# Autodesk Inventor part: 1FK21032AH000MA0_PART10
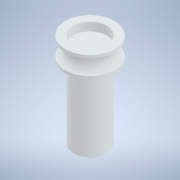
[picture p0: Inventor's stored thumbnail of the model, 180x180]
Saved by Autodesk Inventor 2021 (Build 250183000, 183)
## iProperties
Created: 2025-04
Part Number: 1FK21032AH000MA0_PART10
Material: Generic
Catalog Web Link: www.3dfindit.com
Description: -Servo synchronous motor
Document SubType Name: Modeling
Designer: psAdmin
Mass: 6.43867 g
Surface Area: 29.6592 cm^2
Volume: 6.43867 cm^3
Density: 1 g/cm^3
Appearance: PSOLRGB-212-217-219
Category: PARTsolutions
Title: 1FK21032AH000MA0_PART10
Author: Cadenas PARTsolutions
Comments: Servo synchronous motor
Sending System: PARTsolutions
Preprocessor: ST-DEVELOPER v19.3
PSOL_IDENT_0: {$CADENAS_DATA/23d-libs/siemens_ag/_cat_/45/10/1fk21032ah000ma0.prj},216 {VTYP=3D},{NB=1FK21032AH000
PSOL_IDENT_1: MA0_PART10},{LINA=1FK21032AH000MA0_PART10},{NN=1FK21032AH000MA0_PART10},{NOPRJ=TRUE},{DATE=19.08.202
PSOL_IDENT_2: 5 14:00:35},{GEOMDATE=30.07.2025 02:02:03},{VERSION=},{LINEID=10},{WBVAR=},{WBNUMERIC=}  {NB=1FK2103
PSOL_IDENT_3: 2AH000MA0_PART10},{LINA=1FK21032AH000MA0_PART10},{KT=DUMMY},{PREVIEW=../../../_pool_/14/8e/p_d211_xx
PSOL_IDENT_4: _00426j.png},{DESCSHORT=SIMOTICS S-1FK2 HD, SINAMICS S210 3AC 400V-480V, 0.59 Nm, 4500 rpm},{DESCLON
PSOL_IDENT_5: G=SIMOTICS S-1FK2 HD servo motor M0=0.64 Nm; PN = 0.28 kW at nN=4500 rpm (380-480 V); PN = 0.167 kW
PSOL_IDENT_6: at nN=2500 rpm (200-240 V); degree of protection IP64; cylindrical shaft D14 x 30 mm; absolute encod
PSOL_IDENT_7: er 22-bit + 12-bit multiturn (encoder AM22DQC); with OCC interface; plug size M17, rotatable; SIMOTI
PSOL_IDENT_8: CS S-1FK2 servomotorfor a wide range of uses in industrial environments. SIMOTICS S‑1FK2 servomotors
PSOL_IDENT_9: are compact synchronous motors with a high dynamic performance that set themselves apart as a resul
PSOL_IDENT_10: t of their high power density, degree of protection and overload capability. The motors are availabl
PSOL_IDENT_11: e in two variants: as High Dynamic variant (highest dynamic performance as a result of the low intri
PSOL_IDENT_12: nsic moment of inertia for applications demanding a high dynamic performance with low moved masses)
PSOL_IDENT_13: - and as Compact variant (precise and stable closed-loop control for medium up to large moved masses
PSOL_IDENT_14: as a result of a medium intrinsic moment of inertia). SIMOTICSS‑1FK2 servomotors fully exploit thei
PSOL_IDENT_15: r strengths in a system with the SINAMICSS210 frequency converter and simple connection using the on
PSOL_IDENT_16: e cable connection (OCC). Advantages include the short control and positioning times, fast and preci
PSOL_IDENT_17: se correction of disturbing quantities as well as stable control with a high dynamic performance. Th
PSOL_IDENT_18: e servo motors can be configured to address a wide range of requirements. For example with and witho
PSOL_IDENT_19: ut holding brake, IP64 or IP65 degree of protection, singleturn or multiturn absolute encoders - to
PSOL_IDENT_20: name just a few. Further, the servomotors are available in different shaft heights extending from 20
PSOL_IDENT_21: to 100. A shaft sealing ring is available to achieve an IP65 degree of protection and for subsequen
PSOL_IDENT_22: t mounting at the motor or as spare part. SIMOTICS - the optimum motor for each and every motion con
PSOL_IDENT_23: trol application.},{INTNO=195125335004},{SUPPLIERALTNO=1FK2103-2AH00-0MA0},{MANUID=1FK21032AH000MA0}
PSOL_IDENT_24: ,{MANUNAME=Siemens},{MANUTYPEDESC=SYNCHRONOUS MOTOR 1FK2 HD 0,64 NM},{AAU732=SIMOTICS},{AAO057=S-1FK
PSOL_IDENT_25: 2},{AAU734=SIMOTICS S-1FK2 HD servo motor M0=0.64 Nm; PN = 0.28 kW at nN=4500 rpm (380-480 V); PN =
PSOL_IDENT_26: 0.167 kW at nN=2500 rpm (200-240 V); degree of protection IP64; cylindrical shaft D14 x 30 mm; absol
PSOL_IDENT_27: ute encoder 22-bit + 12-bit multiturn (encoder AM22DQC); with OCC interface; plug size M17, rotatabl
PSOL_IDENT_28: e;},{AAW338=SYNCHRONOUS MOTOR 1FK2 HD 0,64 NM},{AAO742=SIMOTICS},{AAO663=4034106444624},{NOCUPEROU=1
PSOL_IDENT_29: },{PRICEQUANTITY=1},{QUANTITYMIN=1},{QUANTITYINT=1},{CTN=85015100},{COO=RO},{AAO676=1FK2103-2AH00-0M
PSOL_IDENT_30: A0},{AAO677=Siemens AG},{ORDERUNIT=C62},{CONTENTUNIT=C62}
NB: 1FK21032AH000MA0_PART10
NT: Servo synchronous motor
NBSYN: $MANUID._PART10
LINA: 1FK21032AH000MA0_PART10
CATALOG: SIEMENS
PREVIEW: ../../../_pool_/14/8e/p_d211_xx_00426j.png
DESCSHORT: SIMOTICS S-1FK2 HD, SINAMICS S210 3AC 400V-480V, 0.59 Nm, 4500 rpm
DESCLONG: SIMOTICS S-1FK2 HD servo motor M0=0.64 Nm; PN = 0.28 kW at nN=4500 rpm (380-480 V); PN = 0.167 kW at nN=2500 rpm (200-240 V); degree of protection IP64; cylindr
INTNO: 195125335004
SUPPLIERALTNO: 1FK2103-2AH00-0MA0
MANUID: 1FK21032AH000MA0
MANUNAME: Siemens
MANUTYPEDESC: SYNCHRONOUS MOTOR 1FK2 HD 0,64 NM
AAU732: SIMOTICS
AAO057: S-1FK2
AAU734: SIMOTICS S-1FK2 HD servo motor M0=0.64 Nm; PN = 0.28 kW at nN=4500 rpm (380-480 V); PN = 0.167 kW at nN=2500 rpm (200-240 V); degree of protection IP64; cylindr
AAW338: SYNCHRONOUS MOTOR 1FK2 HD 0,64 NM
AAO742: SIMOTICS
AAO663: 4034106444624.0
NOCUPEROU: 1
PRICEQUANTITY: 1
QUANTITYMIN: 1
QUANTITYINT: 1
CTN: 85015100
COO: RO
ARTICLENO: 1FK21032AH000MA0_PART10
BOMINFO: 1FK21032AH000MA0_PART10
CREATOR: CADENAS GmbH
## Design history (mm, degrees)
feature "2025_04_17_15_00_20_0760"
body "Solid1"
